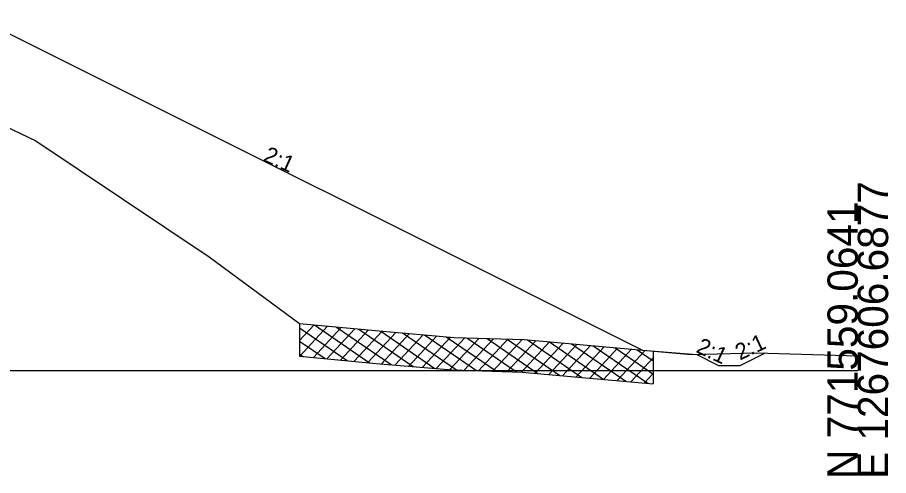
# Model space of a CAD drawing. Extents: x -3833 to 1267678, y -522 to 773248.
# Drawn here: x 222.5 to 302.8, y 7990.3 to 8032.6 of the extents above; entities that cross this region are included whole.
import ezdxf

# ---------------------------------------------------------------- set-up
doc = ezdxf.new("R2010")
doc.units = 0
for name, color, linetype in [('Exist Cross Section Cell', 7, 'Continuous'), ('Exist XS Ground Line', 7, 'Continuous'), ('Prop CMT DNC', 7, 'Continuous'), ('Prop XS Ditch Slope Text', 7, 'Continuous'), ('Prop XS Finish Grade', 7, 'Continuous'), ('Prop XS Label Text', 7, 'Continuous'), ('Prop XS Undercut Exc', 7, 'Continuous')]:
    doc.layers.add(name, color=color, linetype=linetype)

msp = doc.modelspace()

# ---------------------------------------------------------------- linework, layer by layer
at = {"layer": 'Exist Cross Section Cell'}
msp.add_line((150, 8000), (300, 8000), dxfattribs=at)
at = {"layer": 'Exist XS Ground Line'}
for p, q in [((214.31, 8025.911), (224.17, 8021.213)), ((224.17, 8021.213), (240.182, 8010.505)), ((240.182, 8010.505), (248.502, 8004.34)), ((248.502, 8004.34), (255.841, 8003.654)), ((255.841, 8003.654), (262.761, 8003.064)), ((262.761, 8003.064), (269.224, 8002.853)), ((269.224, 8002.853), (284.624, 8001.484)), ((284.624, 8001.484), (290.667, 8001.634)), ((290.667, 8001.634), (300, 8001.37))]:
    msp.add_line(p, q, dxfattribs=at)
at = {"layer": 'Prop XS Finish Grade'}
msp.add_line((218.725, 8032.598), (280.14, 8001.89), dxfattribs=at)
msp.add_lwpolyline([(280.14, 8001.89), (285.14, 8001.473), (287.14, 8000.473), (289.14, 8000.473), (291.422, 8001.615)], dxfattribs=at)
at = {"layer": 'Prop XS Undercut Exc'}
for p, q in [((248.502, 8004.34), (248.516, 8001.326)), ((248.504, 8003.947), (252.906, 8000.915)), ((249.842, 8004.215), (248.509, 8002.776)), ((251.097, 8004.098), (248.528, 8001.324)), ((252.351, 8003.98), (249.782, 8001.207)), ((249.884, 8004.211), (254.947, 8000.725)), ((253.606, 8003.863), (251.037, 8001.09)), ((251.924, 8004.02), (256.968, 8000.547)), ((254.861, 8003.746), (252.292, 8000.973)), ((253.964, 8003.83), (258.98, 8000.376)), ((256.117, 8003.631), (253.546, 8000.856)), ((257.38, 8003.523), (254.801, 8000.738)), ((256.002, 8003.641), (260.993, 8000.204)), ((258.644, 8003.415), (256.059, 8000.625)), ((259.907, 8003.307), (257.322, 8000.517)), ((258.014, 8003.469), (262.972, 8000.055)), ((261.17, 8003.2), (258.585, 8000.409)), ((262.418, 8003.075), (259.849, 8000.301)), ((260.027, 8003.297), (264.823, 7999.995)), ((263.741, 8003.032), (261.112, 8000.194)), ((262.04, 8003.125), (266.674, 7999.935)), ((265.065, 8002.989), (262.375, 8000.086)), ((266.388, 8002.945), (263.689, 8000.032)), ((263.949, 8003.025), (268.525, 7999.874)), ((267.711, 8002.902), (265.012, 7999.989)), ((265.8, 8002.965), (270.501, 7999.728)), ((267.651, 8002.904), (272.526, 7999.548)), ((248.509, 8002.729), (250.866, 8001.106)), ((269.034, 8002.859), (266.335, 7999.946)), ((270.303, 8002.757), (267.658, 7999.902)), ((271.562, 8002.645), (268.984, 7999.862)), ((269.528, 8002.826), (274.55, 7999.368)), ((272.822, 8002.533), (270.244, 7999.75)), ((274.081, 8002.421), (271.503, 7999.638)), ((271.553, 8002.646), (276.575, 7999.188)), ((275.341, 8002.309), (272.763, 7999.527)), ((273.577, 8002.466), (278.6, 7999.008)), ((276.6, 8002.197), (274.022, 7999.415)), ((277.86, 8002.085), (275.282, 7999.303)), ((275.602, 8002.286), (280.624, 7998.828)), ((277.627, 8002.106), (281.192, 7999.651)), ((248.515, 8001.511), (248.826, 8001.297)), ((248.516, 8001.326), (255.574, 8000.666)), ((279.119, 8001.973), (276.541, 7999.191)), ((280.378, 8001.861), (277.801, 7999.079)), ((279.651, 8001.926), (281.14, 8000.901)), ((281.14, 8001.794), (281.14, 7998.782)), ((255.574, 8000.666), (262.585, 8000.068)), ((281.112, 8001.182), (279.06, 7998.967)), ((262.585, 8000.068), (269.042, 7999.857)), ((269.042, 7999.857), (281.14, 7998.782)), ((281.14, 7999.741), (280.319, 7998.855))]:
    msp.add_line(p, q, dxfattribs=at)

# ---------------------------------------------------------------- texts
at = {"layer": 'Exist Cross Section Cell'}
for s, p in [('E 1267606.6877', (302.8, 7990)), ('N 771559.0641', (300, 7990))]:
    msp.add_text(s, height=2.8, rotation=90, dxfattribs=at).set_placement(p)
at = {"layer": 'Prop CMT DNC'}
msp.add_text('X', height=0.00025, dxfattribs=at).set_placement((276.616, 8002.196))
at = {"layer": 'Prop XS Ditch Slope Text'}
msp.add_text('2:1', height=1.5, rotation=335.81005, dxfattribs=at).set_placement((245.068, 8019.384))
at = {"layer": 'Prop XS Label Text'}
for rotation, p in [(335.06327, (284.996, 8001.73)), (24.93673, (289.128, 8000.924))]:
    msp.add_text('2:1', height=1.5, rotation=rotation, dxfattribs=at).set_placement(p)

doc.saveas('drawing.dxf')
